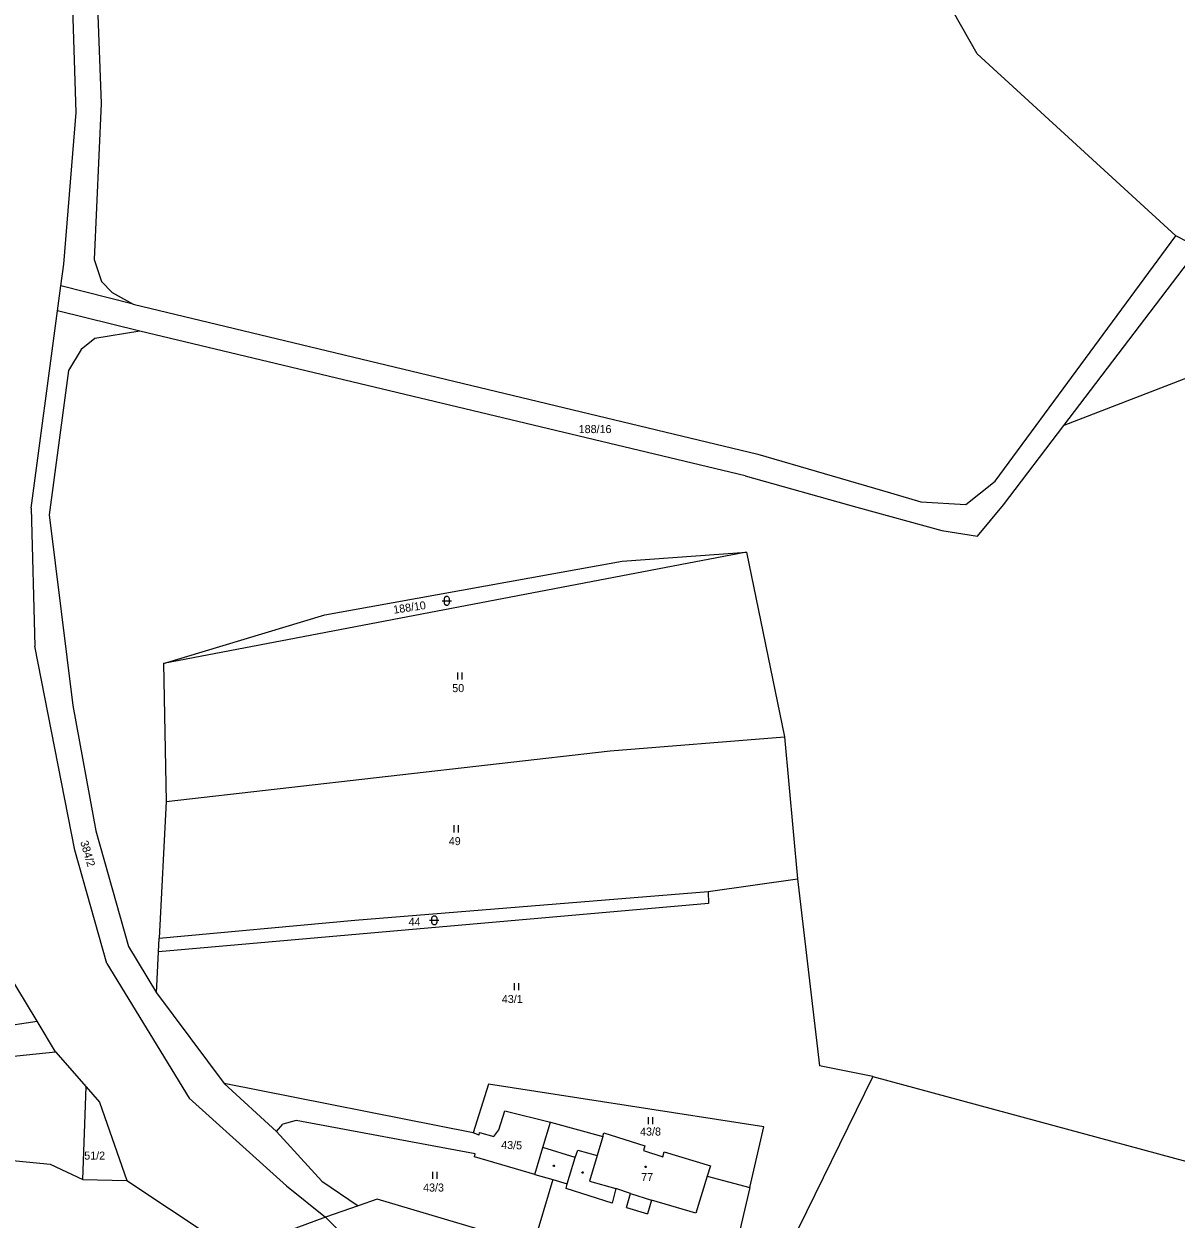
# Model space of a CAD drawing. Extents: x -811039 to -805820, y -1161436 to -1155864.
# Drawn here: x -806537.2 to -806292.6, y -1157981.5 to -1157727.6 of the extents above; entities that cross this region are included whole.
import ezdxf

# ---------------------------------------------------------------- set-up
doc = ezdxf.new("R2010")
doc.units = 0
for name, color, linetype in [('Default', 7, 'Continuous'), ('KN_HRANICE', 7, 'Continuous'), ('KN_KULTURY', 7, 'Continuous'), ('KN_PARCELY', 7, 'Continuous'), ('KN_SLUCKY', 7, 'Continuous')]:
    doc.layers.add(name, color=color, linetype=linetype)

# ---------------------------------------------------------------- blocks, each defined once
blk = doc.blocks.new('306')
at = {"layer": 'Default'}
for p, q in [((-0.5, 1.5), (-0.5, 0)), ((0.5, 0), (0.5, 1.5))]:
    blk.add_line(p, q, dxfattribs=at)
blk = doc.blocks.new('316')
at = {"layer": 'Default'}
for points in [[(-1, 1), (0.27, 1), (1, 1)], [(-0.5, 1.5), (-0.4, 1.79), (-0.15, 1.97), (0.16, 1.97), (0.41, 1.79), (0.51, 1.5), (0.51, 0.5), (0.41, 0.21), (0.16, 0.03), (-0.15, 0.03), (-0.4, 0.21), (-0.5, 0.5), (-0.5, 1.5)]]:
    blk.add_lwpolyline(points, dxfattribs=at)
blk = doc.blocks.new('402')
at = {"layer": 'Default'}
blk.add_lwpolyline([(0.09, 0.15), (0.18, 0), (0.09, -0.15), (-0.09, -0.15), (-0.18, 0), (-0.09, 0.15), (0.09, 0.15)], dxfattribs=at)

msp = doc.modelspace()

# ---------------------------------------------------------------- linework, layer by layer
at = {"layer": 'KN_HRANICE'}
for p, q in [((-806334.8, -1157733.98), (-806369.85, -1157671.95)), ((-806526.14, -1157746.49), (-806527.36, -1157709)), ((-806522.05, -1157712.53), (-806520.82, -1157744.55)), ((-806292.59, -1157772.68), (-806334.8, -1157733.98)), ((-806528.76, -1157778.68), (-806526.14, -1157746.49)), ((-806520.82, -1157744.55), (-806522.31, -1157777.7)), ((-806330.97, -1157824.79), (-806292.59, -1157772.68)), ((-806287.65, -1157775.18), (-806292.59, -1157772.68)), ((-806316.4, -1157812.94), (-806287.65, -1157775.18)), ((-806529.38, -1157783.31), (-806528.76, -1157778.68)), ((-806522.31, -1157777.7), (-806520.78, -1157782.33)), ((-806530.09, -1157788.59), (-806529.38, -1157783.31)), ((-806514.04, -1157787.19), (-806529.38, -1157783.31)), ((-806520.78, -1157782.33), (-806518.52, -1157784.69)), ((-806518.52, -1157784.69), (-806514.04, -1157787.19)), ((-806514.04, -1157787.19), (-806381.37, -1157819.05)), ((-806535.68, -1157830.51), (-806530.09, -1157788.59)), ((-806512.61, -1157792.88), (-806530.09, -1157788.59)), ((-806257.74, -1157790.3), (-806316.4, -1157812.94)), ((-806522.14, -1157794.46), (-806525.1, -1157796.8)), ((-806512.61, -1157792.88), (-806522.14, -1157794.46)), ((-806384.1, -1157823.65), (-806512.61, -1157792.88)), ((-806525.1, -1157796.8), (-806527.8, -1157801.25)), ((-806527.8, -1157801.25), (-806531.86, -1157831.91)), ((-806329.24, -1157829.81), (-806316.4, -1157812.94)), ((-806381.37, -1157819.05), (-806353.2, -1157827.23)), ((-806384.1, -1157823.65), (-806360.37, -1157830.3)), ((-806337.22, -1157829.69), (-806330.97, -1157824.79)), ((-806353.2, -1157827.23), (-806346.79, -1157829.18)), ((-806360.37, -1157830.3), (-806342.28, -1157835.26)), ((-806346.79, -1157829.18), (-806337.22, -1157829.69)), ((-806334.75, -1157836.41), (-806329.24, -1157829.81)), ((-806535.68, -1157830.51), (-806534.91, -1157859.83)), ((-806531.86, -1157831.91), (-806526.83, -1157872.37)), ((-806342.28, -1157835.26), (-806334.75, -1157836.41)), ((-806383.79, -1157839.85), (-806507.59, -1157863.46)), ((-806410.21, -1157841.74), (-806383.79, -1157839.85)), ((-806383.79, -1157839.85), (-806375.72, -1157879.06)), ((-806473.34, -1157853.13), (-806410.21, -1157841.74)), ((-806507.59, -1157863.46), (-806473.34, -1157853.13)), ((-806526.44, -1157903.12), (-806534.91, -1157859.83)), ((-806507.59, -1157863.46), (-806507.02, -1157892.82)), ((-806526.83, -1157872.37), (-806521.94, -1157899)), ((-806412.71, -1157882), (-806375.72, -1157879.06)), ((-806375.72, -1157879.06), (-806372.94, -1157909.21)), ((-806507.02, -1157892.82), (-806412.71, -1157882)), ((-806507.02, -1157892.82), (-806508.53, -1157921.81)), ((-806521.94, -1157899), (-806515.04, -1157923.58)), ((-806519.66, -1157927.16), (-806526.44, -1157903.12)), ((-806391.9, -1157911.93), (-806372.94, -1157909.21)), ((-806372.94, -1157909.21), (-806368.28, -1157948.94)), ((-806466.96, -1157918.01), (-806391.9, -1157911.93)), ((-806391.9, -1157911.93), (-806391.88, -1157914.43)), ((-806391.88, -1157914.43), (-806508.67, -1157924.72)), ((-806534.45, -1157939.44), (-806547.36, -1157918.12)), ((-806508.53, -1157921.81), (-806466.96, -1157918.01)), ((-806515.04, -1157923.58), (-806509.08, -1157933.39)), ((-806508.67, -1157924.72), (-806508.53, -1157921.81)), ((-806509.08, -1157933.39), (-806508.67, -1157924.72)), ((-806519.66, -1157927.16), (-806502.17, -1157955.78)), ((-806509.08, -1157933.39), (-806494.73, -1157952.71)), ((-806573.34, -1157945.48), (-806534.45, -1157939.44)), ((-806530.51, -1157945.95), (-806534.45, -1157939.44)), ((-806553.43, -1157948.32), (-806530.51, -1157945.95)), ((-806530.51, -1157945.95), (-806524.04, -1157953.41)), ((-806356.95, -1157951.21), (-806368.28, -1157948.94)), ((-806356.95, -1157951.21), (-806381.62, -1158001.34)), ((-806356.95, -1157951.21), (-806280.78, -1157971.8)), ((-806524.69, -1157973.05), (-806524.04, -1157953.41)), ((-806524.04, -1157953.41), (-806521.21, -1157956.67)), ((-806441.82, -1157963.17), (-806494.73, -1157952.71)), ((-806494.73, -1157952.71), (-806483.6, -1157962.9)), ((-806438.6, -1157952.82), (-806441.82, -1157963.17)), ((-806380.1, -1157961.87), (-806438.6, -1157952.82)), ((-806521.21, -1157956.67), (-806515.35, -1157973.25)), ((-806502.17, -1157955.78), (-806481.48, -1157974.4)), ((-806436.4, -1157962.49), (-806435.1, -1157958.46)), ((-806435.1, -1157958.46), (-806425.42, -1157960.91)), ((-806483.6, -1157962.9), (-806482.26, -1157961.34)), ((-806479.4, -1157960.55), (-806482.26, -1157961.34)), ((-806441.41, -1157967.64), (-806479.4, -1157960.55)), ((-806427.05, -1157966.25), (-806425.42, -1157960.91)), ((-806425.42, -1157960.91), (-806414.28, -1157963.91)), ((-806383.1, -1157974.77), (-806380.1, -1157961.87)), ((-806483.6, -1157962.9), (-806473.99, -1157973.45)), ((-806440.58, -1157963.65), (-806441.82, -1157963.17)), ((-806440.58, -1157963.65), (-806440.48, -1157963.1)), ((-806440.48, -1157963.1), (-806437.43, -1157963.91)), ((-806437.43, -1157963.91), (-806436.4, -1157962.49)), ((-806414.28, -1157963.91), (-806414.05, -1157963.19)), ((-806414.05, -1157963.19), (-806405.36, -1157965.91)), ((-806428.74, -1157971.97), (-806427.05, -1157966.25)), ((-806405.36, -1157965.91), (-806405.64, -1157966.93)), ((-806405.64, -1157966.93), (-806401.56, -1157968.23)), ((-806401.56, -1157968.23), (-806401.24, -1157967.18)), ((-806401.24, -1157967.18), (-806391.41, -1157970.14)), ((-806541.08, -1157968.88), (-806531.68, -1157969.79)), ((-806531.68, -1157969.79), (-806524.69, -1157973.05)), ((-806441.54, -1157968.22), (-806441.41, -1157967.64)), ((-806428.74, -1157971.97), (-806441.54, -1157968.22)), ((-806428.74, -1157971.97), (-806424.9, -1157973.07)), ((-806392.12, -1157972.38), (-806394.53, -1157980.23)), ((-806391.41, -1157970.14), (-806392.12, -1157972.38)), ((-806392.12, -1157972.38), (-806383.1, -1157974.77)), ((-806524.69, -1157973.05), (-806515.35, -1157973.25)), ((-806515.35, -1157973.25), (-806497.28, -1157985.34)), ((-806481.48, -1157974.4), (-806473.17, -1157981.08)), ((-806473.99, -1157973.45), (-806466.25, -1157978.68)), ((-806424.9, -1157973.07), (-806429.06, -1157987.06)), ((-806424.9, -1157973.07), (-806421.84, -1157973.96)), ((-806422.11, -1157975.01), (-806421.84, -1157973.96)), ((-806412.34, -1157978.08), (-806422.11, -1157975.01)), ((-806411.53, -1157974.97), (-806412.34, -1157978.08)), ((-806408.41, -1157976.03), (-806411.53, -1157974.97)), ((-806383.1, -1157974.77), (-806388.68, -1157998.88)), ((-806462.21, -1157977.22), (-806466.25, -1157978.68)), ((-806429.06, -1157987.06), (-806462.21, -1157977.22)), ((-806409.28, -1157979.02), (-806408.41, -1157976.03)), ((-806403.94, -1157977.42), (-806404.81, -1157980.34)), ((-806394.53, -1157980.23), (-806403.94, -1157977.42)), ((-806466.25, -1157978.68), (-806473.17, -1157981.08)), ((-806409.28, -1157979.02), (-806404.81, -1157980.34)), ((-806473.17, -1157981.08), (-806492.48, -1157988.16)), ((-806473.17, -1157981.08), (-806466.66, -1157987.53))]:
    msp.add_line(p, q, dxfattribs=at)
at = {"layer": 'KN_SLUCKY'}
for p, q in [((-806414.28, -1157963.91), (-806415.51, -1157967.95)), ((-806420.16, -1157968.41), (-806427.05, -1157966.25)), ((-806420.16, -1157968.41), (-806419.62, -1157966.81)), ((-806419.62, -1157966.81), (-806415.51, -1157967.95)), ((-806421.84, -1157973.96), (-806420.16, -1157968.41)), ((-806415.51, -1157967.95), (-806417.12, -1157973.4)), ((-806417.12, -1157973.4), (-806411.53, -1157974.97)), ((-806408.41, -1157976.03), (-806403.94, -1157977.42))]:
    msp.add_line(p, q, dxfattribs=at)

# ---------------------------------------------------------------- block references
at = {"layer": 'KN_KULTURY'}
for name, p in [('316', (-806447.45, -1157851.17)), ('306', (-806444.65, -1157866.86)), ('306', (-806445.43, -1157899.35)), ('316', (-806450.09, -1157919.02)), ('306', (-806432.66, -1157932.88)), ('306', (-806404.16, -1157961.34)), ('306', (-806449.98, -1157972.93)), ('402', (-806424.69, -1157970.17)), ('402', (-806418.61, -1157971.6)), ('402', (-806405.23, -1157970.36))]:
    msp.add_blockref(name, p, dxfattribs=at)

# ---------------------------------------------------------------- texts
at = {"layer": 'KN_PARCELY'}
for s, p in [('188/16', (-806419.42, -1157814.55)), ('50', (-806446.27, -1157869.56)), ('49', (-806447.01, -1157902.05)), ('44', (-806455.55, -1157919.19)), ('43/1', (-806435.74, -1157935.58)), ('43/8', (-806406.38, -1157963.73)), ('51/2', (-806524.42, -1157968.84)), ('77', (-806406.14, -1157973.38)), ('43/3', (-806452.46, -1157975.62))]:
    msp.add_text(s, height=1.7, dxfattribs=at).set_placement(p)
for s, rotation, p in [('188/10', 8.365, (-806458.67, -1157852.91)), ('384/2', 286.536, (-806525.29, -1157901.37)), ('43/5', 357.984, (-806435.9, -1157966.53))]:
    msp.add_text(s, height=1.7, rotation=rotation, dxfattribs=at).set_placement(p)

doc.saveas('drawing.dxf')
